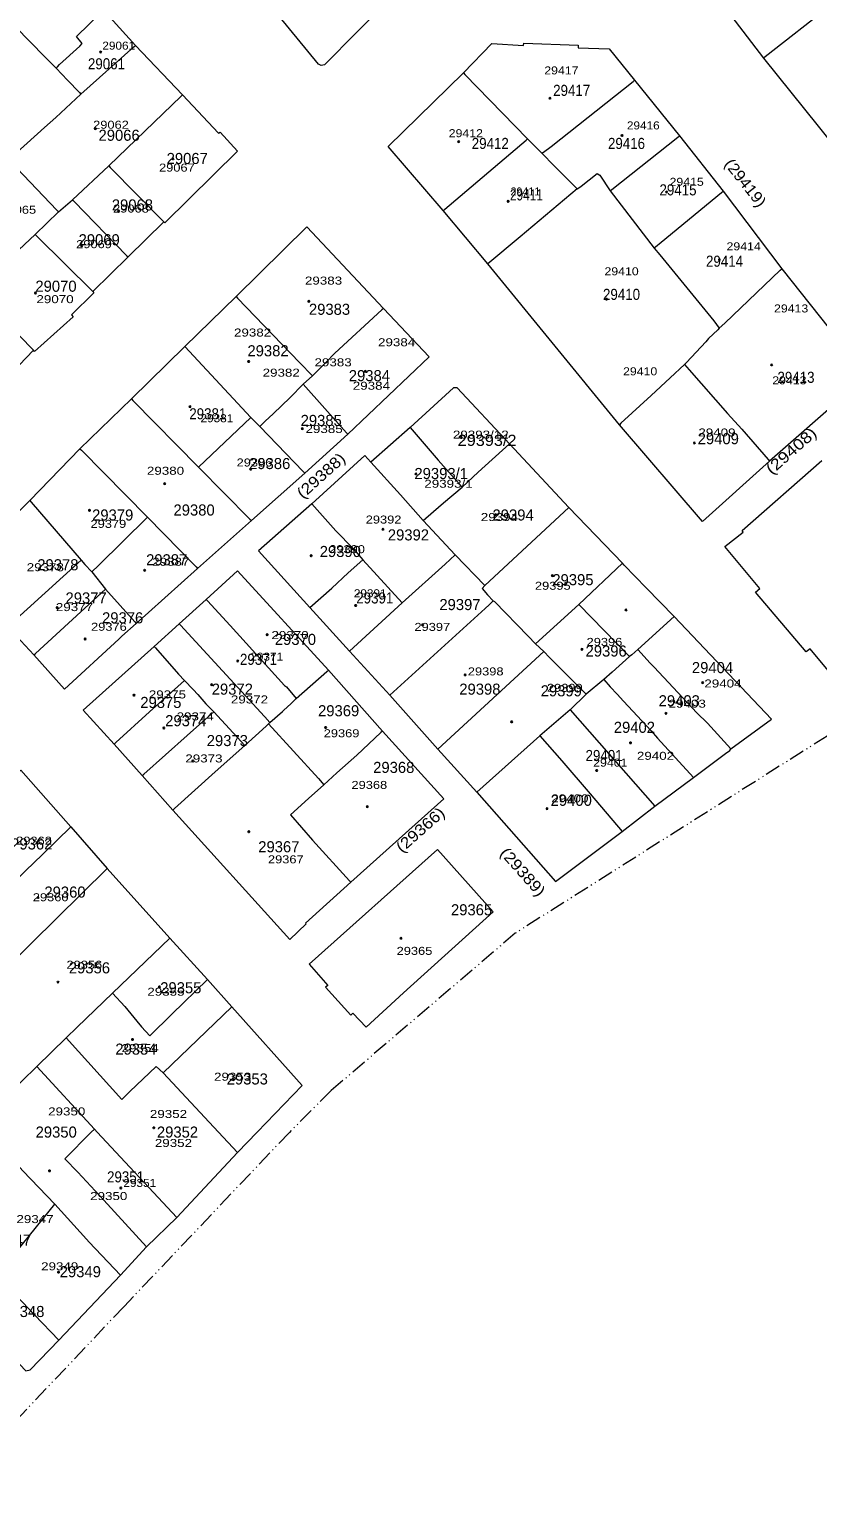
# Model space of a CAD drawing. Extents: x 650553 to 652508, y 239277 to 241647.
# Drawn here: x 651029.3 to 651285.4, y 239630 to 240108.2 of the extents above; entities that cross this region are included whole.
import ezdxf

# ---------------------------------------------------------------- set-up
doc = ezdxf.new("R2010")
doc.units = 0
doc.header["$PDMODE"] = 32
doc.header["$PDSIZE"] = 0.5
doc.linetypes.add('DASH_DOUBLE_DOT', pattern=[9.2, 5, -1.2, 0.3, -1.2, 0.3, -1.2])
for name, color, linetype in [('19', 7, 'Continuous'), ('20', 7, 'Continuous'), ('44', 7, 'Continuous'), ('6', 7, 'Continuous')]:
    doc.layers.add(name, color=color, linetype=linetype)
for name, color, linetype, lineweight in [('3', 7, 'Continuous', 13), ('5', 7, 'Continuous', 13), ('52', 7, 'DASH_DOUBLE_DOT', 13)]:
    doc.layers.add(name, color=color, linetype=linetype, lineweight=lineweight)

msp = doc.modelspace()

# ---------------------------------------------------------------- linework, layer by layer
at = {"layer": '3'}
for p, q in [((651178.3, 240032.05), (651163.79, 240049.38)), ((651301.48, 239995.66), (651269.84, 239967.99))]:
    msp.add_line(p, q, dxfattribs=at)
for points in [[(651146.21, 240118.01), (651125.2, 240096.68), (651124.15, 240096.5), (651123.22, 240096.94), (651100.89, 240124.15), (651084.81, 240142.79), (651068.91, 240161.72)], [(651014.69, 240119.32), (651031.37, 240136.47), (651033.06, 240136.27), (651053.41, 240114.49), (651063.76, 240102.95), (651079.09, 240086.95)], [(651244.93, 240128.08), (651253.33, 240117.93), (651267.91, 240098.88), (651285.64, 240076.82), (651301.47, 240056.95)], [(651170.33, 240094.05), (651179.61, 240103.61), (651189.88, 240103.02), (651189.94, 240103.72), (651207.67, 240103.1), (651207.61, 240102.24), (651217.69, 240101.92)], [(651217.69, 240101.92), (651225.95, 240091.72), (651240.57, 240073.58), (651254.7, 240055.63), (651273.8, 240030.45), (651301.48, 239995.66)], [(651163.79, 240049.38), (651145.92, 240070.2), (651170.33, 240094.05)], [(651079.09, 240086.95), (651090.77, 240074.52), (651091.28, 240074.79), (651096.87, 240068.6), (651073.27, 240045.33), (651072.98, 240045.66), (651061.347, 240034.304), (651049.86, 240023.09)], [(651079.8, 240005.23), (651096.45, 240021.44), (651119.4, 240044.04), (651144.33, 240017.58), (651159.24, 240001.88)], [(651269.84, 239967.99), (651248.04, 239948.37), (651221.04, 239979.79), (651178.3, 240032.05)], [(651049.86, 240023.09), (651050.21, 240022.68), (651042.96, 240015.47), (651043.52, 240014.85), (651030.93, 240003.62), (651030.64, 240004.03)], [(650963.63, 239979.83), (650963.19, 239979.42), (650984.08, 239956.68), (651007.923, 239979.861), (651007.45, 239980.27), (651019.018, 239991.973), (651030.64, 240004.03)], [(651079.8, 240005.23), (651062.449, 239988.199), (651045.708, 239971.989), (651029.394, 239955.14)], [(651063.98, 239915.24), (651067.961, 239918.8), (651083.95, 239933.1), (651101.47, 239948.63), (651118.77, 239964.05), (651132.76, 239976.69), (651159.24, 240001.88)], [(651294.154, 239893.589), (651283.07, 239907.03), (651281.72, 239905.99), (651265.26, 239925.42), (651266.66, 239926.6), (651255.322, 239940.281), (651261.29, 239944.93), (651260.89, 239945.47), (651286.79, 239968.16)], [(651029.394, 239955.14), (651011.428, 239937.153), (651010.901, 239937.895), (651005.075, 239932.349), (651009.776, 239926.918), (651010.311, 239927.45), (651022.23, 239914.101), (651030.731, 239905.003)], [(651086.75, 239923.04), (651096.89, 239932.32), (651126.46, 239900.08), (651144.02, 239880.27)], [(651046.81, 239887.11), (651069.8, 239907.8), (651077.97, 239915.13), (651086.75, 239923.04)], [(651030.731, 239905.003), (651040.74, 239893.93), (651058.4, 239910.11), (651059.31, 239911.07), (651063.98, 239915.24)], [(651133.77, 239831.17), (651119.06, 239817.88), (651119.22, 239817.67), (651113.96, 239812.53), (651075.92, 239854.63), (651065.92, 239865.85), (651056.86, 239876.06), (651046.81, 239887.11)], [(651144.02, 239880.27), (651163.99, 239858.27), (651154.68, 239849.922), (651133.77, 239831.17)], [(651000, 239839.83), (651003.18, 239842.9), (651002.08, 239844.3), (651026.48, 239867.54), (651042.7, 239849.13), (651054.6, 239835.68), (651074.89, 239813.04), (651087.13, 239799.56), (651095.02, 239790.72), (651117.9, 239765.17), (651103.31, 239750)], [(651161.96, 239841.85), (651120.21, 239804.61), (651126.28, 239797.58), (651125.52, 239797.04), (651133.7, 239787.96), (651134.35, 239788.6), (651138.68, 239784.1)], [(651138.68, 239784.1), (651150.81, 239795.25), (651180.03, 239821.6), (651161.96, 239841.85)], [(651000, 239701.81), (651009.47, 239692.08), (651028.09, 239672.47), (651029.48, 239672.78), (651038.83, 239682.45), (651058.85, 239703.52), (651067.38, 239712.72), (651077.17, 239722.24), (651096.93, 239743.36), (651103.31, 239750)]]:
    msp.add_lwpolyline(points, dxfattribs=at)
msp.add_lwpolyline([(651168.27, 239991.75), (651167.09, 239991.75), (651152.99, 239978.92), (651140.3, 239967.61), (651138.29, 239969.77), (651121.12, 239954.05), (651103.76, 239938.81), (651120.39, 239920.4), (651133.33, 239906.2), (651146.38, 239891.99), (651161.99, 239874.45), (651174.68, 239860.43), (651200.26, 239831.38), (651221.98, 239847.7), (651232.51, 239855.84), (651245.06, 239865.24), (651255.49, 239872.96), (651256.94, 239874), (651257.24, 239874.46), (651270.44, 239884.15), (651238.78, 239917.53), (651229.71, 239926.8), (651222.6, 239934.14), (651222.04, 239934.78), (651204.63, 239952.95), (651185.35, 239973.63)], close=True, dxfattribs=at)
at = {"layer": '44'}
msp.add_point((651223.163, 239919.63), dxfattribs=at)
at = {"layer": '5'}
for p, q in [((651117.05, 240000), (651121.24, 239995.65)), ((651101.26, 239982.09), (651084.27, 239966.04)), ((651177.27, 239927.53), (651204.63, 239952.95)), ((651207.89, 239921.39), (651224.33, 239904.48)), ((651196.49, 239906.1), (651161.99, 239874.45)), ((651205.01, 239887.21), (651232.51, 239855.84)), ((651072.72, 239769.3), (651090.73, 239750)), ((651049.41, 239750), (651050.41, 239751)), ((651051.34, 239750), (651077.17, 239722.24)), ((651090.73, 239750), (651096.93, 239743.36))]:
    msp.add_line(p, q, dxfattribs=at)
for points in [[(651014.69, 240119.32), (651015.181, 240118.82), (651034.33, 240099.34), (651038, 240095.56)], [(651292.21, 240117.87), (651291.71, 240117.48), (651289.7, 240115.91), (651268.41, 240099.271), (651267.91, 240098.88)], [(651038, 240095.56), (651038.454, 240096.06), (651039.09, 240096.76), (651045.68, 240102.8), (651046.44, 240103.65), (651044.58, 240105.87), (651052.91, 240114.002), (651053.41, 240114.49)], [(651046.01, 240087.16), (651063.26, 240102.505), (651063.76, 240102.95)], [(651038, 240095.56), (651041.65, 240091.75), (651045.535, 240087.66), (651046.01, 240087.16)], [(651170.33, 240094.05), (651170.817, 240093.55), (651191.2, 240072.64), (651195.86, 240067.97)], [(651195.86, 240067.97), (651196.36, 240068.335), (651198.83, 240070.14), (651225.45, 240091.322), (651225.95, 240091.72)], [(651022.59, 240065.87), (651025.24, 240068.24), (651034.21, 240076.35), (651037.83, 240079.55), (651046.01, 240087.16)], [(651055.09, 240063.85), (651078.59, 240086.469), (651079.09, 240086.95)], [(651218.08, 240055.75), (651218.58, 240056.146), (651240.07, 240073.184), (651240.57, 240073.58)], [(651163.79, 240049.38), (651164.29, 240049.804), (651190.7, 240072.216), (651191.2, 240072.64)], [(650998.84, 240012), (651011.61, 240023.38), (651031.17, 240041.53), (651038.69, 240048.96), (651043.31, 240052.81), (651055.09, 240063.85)], [(651022.59, 240065.87), (651023.066, 240065.37), (651038.214, 240049.46), (651038.69, 240048.96)], [(651055.09, 240063.85), (651055.582, 240063.35), (651072.98, 240045.66)], [(651195.86, 240067.97), (651199.88, 240063.83), (651207.3, 240056.4)], [(651207.3, 240056.4), (651207.8, 240056.731), (651208.57, 240057.24), (651213.83, 240061.34), (651214.64, 240060.82), (651218.08, 240055.75), (651232.29, 240037.13)], [(651207.3, 240056.4), (651188.75, 240040.77), (651178.3, 240032.05)], [(651232.29, 240037.13), (651232.79, 240037.536), (651234.64, 240039.04), (651254.2, 240055.216), (651254.7, 240055.63)], [(651043.31, 240052.81), (651043.797, 240052.31), (651060.86, 240034.804), (651061.347, 240034.304)], [(651031.17, 240041.53), (651031.67, 240041.037), (651049.86, 240023.09)], [(651232.29, 240037.13), (651234.21, 240034.97), (651251.72, 240013.58), (651253.47, 240011.13)], [(651253.47, 240011.13), (651255.28, 240012.81), (651273.3, 240029.974), (651273.8, 240030.45)], [(651011.61, 240023.38), (651012.102, 240022.88), (651030.64, 240004.03)], [(651096.45, 240021.44), (651096.93, 240020.94), (651117.05, 240000)], [(651144.33, 240017.58), (651143.83, 240017.117), (651128.58, 240003), (651125.58, 240000)], [(651253.47, 240011.13), (651252.97, 240010.649), (651249.99, 240007.78), (651249.17, 240006.71), (651242.81, 240000)], [(651079.8, 240005.23), (651101.26, 239982.09), (651101.63, 239981.68), (651104.14, 239979.23)], [(651125.58, 240000), (651121.24, 239995.65), (651118.3, 239992.97), (651114.07, 239988.67), (651108.46, 239983.27), (651105.95, 239980.97), (651104.14, 239979.23)], [(651242.81, 240000), (651242.2, 239999.36), (651237.54, 239995.03), (651231.31, 239989.29)], [(651242.2, 239999.36), (651243.65, 239997.64), (651256.16, 239983.44), (651260.83, 239978.29)], [(651118.3, 239992.97), (651132.316, 239977.19), (651132.76, 239976.69)], [(651062.449, 239988.199), (651062.941, 239987.699), (651084.27, 239966.04)], [(651231.31, 239989.29), (651221.54, 239980.253), (651221.04, 239979.79)], [(651104.14, 239979.23), (651118.288, 239964.55), (651118.77, 239964.05)], [(651152.99, 239978.92), (651162.13, 239968.22), (651169.91, 239959.54)], [(651260.83, 239978.29), (651269.403, 239968.49), (651269.84, 239967.99)], [(651157.3, 239948.69), (651160.64, 239951.57), (651163.91, 239954.38), (651169.91, 239959.54), (651175.17, 239964.33), (651185.35, 239973.63)], [(651045.708, 239971.989), (651046.202, 239971.489), (651067.66, 239949.79)], [(651084.27, 239966.04), (651100.976, 239949.13), (651101.47, 239948.63)], [(651140.3, 239967.61), (651149.84, 239956.99), (651157.3, 239948.69), (651167.62, 239937.56), (651177.27, 239927.53), (651176.41, 239926.54), (651178.14, 239924.57), (651179.99, 239922.6), (651180.39, 239922.41), (651191.41, 239911.06), (651193.79, 239908.56), (651196.49, 239906.1), (651198.36, 239904.19), (651206.33, 239896.2), (651210.21, 239892.24)], [(651029.394, 239955.14), (651029.827, 239954.64), (651046.15, 239935.78), (651047.3, 239934.35), (651049.54, 239931.95), (651054, 239926.42)], [(651121.12, 239954.05), (651128.9, 239945.37), (651134.46, 239939.55), (651137.69, 239935.94), (651150.39, 239921.89)], [(651049.54, 239931.95), (651051.7, 239934.03), (651067.66, 239949.79)], [(651067.66, 239949.79), (651083.462, 239933.6), (651083.95, 239933.1)], [(651022.23, 239914.101), (651022.73, 239914.554), (651046.15, 239935.78)], [(651120.39, 239920.4), (651127.61, 239926.74), (651132.9, 239931.66), (651137.69, 239935.94)], [(651133.33, 239906.2), (651150.39, 239921.89), (651164.35, 239934.48), (651167.62, 239937.56)], [(651193.79, 239908.56), (651207.89, 239921.39), (651222.04, 239934.78)], [(651030.731, 239905.003), (651031.231, 239905.463), (651054, 239926.42)], [(651054, 239926.42), (651063.534, 239915.74), (651063.98, 239915.24)], [(651086.75, 239923.04), (651087.205, 239922.54), (651094.51, 239914.52), (651112.15, 239895.09), (651112.85, 239894.63), (651115.97, 239890.83)], [(651146.38, 239891.99), (651177.35, 239920.12), (651178.75, 239921.32), (651179.99, 239922.6)], [(651238.78, 239917.53), (651226.97, 239906.78), (651225.11, 239905.07), (651224.33, 239904.48), (651218.7, 239899.4), (651215.95, 239897.08), (651210.21, 239892.24), (651205.01, 239887.21), (651195.17, 239878.74), (651174.68, 239860.43)], [(651077.97, 239915.13), (651078.429, 239914.63), (651105.64, 239884.96), (651105.8, 239884.86), (651107.43, 239883.02)], [(651069.8, 239907.8), (651070.242, 239907.3), (651077.79, 239898.77), (651079.74, 239896.73), (651082.47, 239893.76), (651083.97, 239892.12), (651086.67, 239889.15), (651089.21, 239886.48), (651099.26, 239875.59)], [(651226.97, 239906.78), (651228.07, 239905.62), (651230.9, 239902.44), (651232.29, 239900.99), (651246.14, 239886.24), (651249.62, 239882.79), (651257.24, 239874.46)], [(651056.86, 239876.06), (651057.36, 239876.515), (651068.34, 239886.51), (651075.38, 239892.8), (651079.74, 239896.73)], [(651115.97, 239890.83), (651125.96, 239899.639), (651126.46, 239900.08)], [(651215.95, 239897.08), (651218.03, 239894.65), (651220.31, 239892.25), (651222.36, 239889.94), (651231.37, 239880.31), (651233.46, 239877.99), (651245.06, 239865.24)], [(651075.92, 239854.63), (651076.42, 239855.083), (651089.61, 239867.04), (651099.26, 239875.59), (651106.24, 239881.87), (651107, 239882.62), (651107.43, 239883.02), (651111.55, 239886.66), (651111.96, 239887.03), (651114.27, 239889.17), (651115.97, 239890.83)], [(651065.92, 239865.85), (651066.42, 239866.294), (651080.58, 239878.86), (651084.6, 239882.37), (651089.21, 239886.48)], [(651107, 239882.62), (651123.22, 239864.89), (651125.01, 239862.78)], [(651144.02, 239880.27), (651143.52, 239879.799), (651135.69, 239872.43), (651129.22, 239866.71), (651125.01, 239862.78), (651119.97, 239858.37), (651114.12, 239853.08), (651121.29, 239844.86)], [(651195.17, 239878.74), (651202.33, 239870.58), (651211.53, 239859.88), (651221.98, 239847.7)], [(651003.18, 239842.9), (651010.69, 239834.98), (651015.18, 239829.88), (651015.37, 239829.53), (651018.95, 239825.92), (651028.04, 239834.93), (651033.56, 239840.23), (651042.7, 239849.13)], [(651121.29, 239844.86), (651133.314, 239831.67), (651133.77, 239831.17)], [(651001.83, 239783.86), (651011.83, 239793.51), (651018.25, 239799.79), (651021.7, 239803.27), (651054.6, 239835.68)], [(651012.96, 239753.01), (651021.99, 239761.78), (651031.72, 239771.33), (651041.21, 239780.58), (651044.83, 239784.08), (651056.34, 239795.18), (651074.89, 239813.04)], [(651056.34, 239795.18), (651060.27, 239790.81), (651064.25, 239786.04), (651065.75, 239784.18), (651068.37, 239781.33), (651075.54, 239788.36), (651087.13, 239799.56)], [(651041.21, 239780.58), (651059.28, 239760.61), (651061.95, 239763.15), (651070.53, 239771.27), (651072.72, 239769.3), (651095.02, 239790.72)], [(651031.72, 239771.33), (651050.41, 239751), (651051.34, 239750)], [(651017.51, 239748.19), (651027.12, 239737.39), (651037.52, 239726.58), (651047.83, 239715.28), (651048.66, 239714.26), (651058.85, 239703.52)], [(651049.41, 239750), (651040.77, 239741.31), (651045, 239736.96), (651053.44, 239727.93), (651067.38, 239712.72)], [(651009.47, 239692.08), (651018.73, 239703.44), (651037.52, 239726.58)], [(651018.73, 239703.44), (651022.99, 239698.95), (651030.9, 239690.63), (651038.83, 239682.45)]]:
    msp.add_lwpolyline(points, dxfattribs=at)
at = {"layer": '52'}
for points in [[(651375.157, 239936.971), (651356.663, 239923.28), (651304.088, 239888.503), (651187.159, 239814.585), (651127.357, 239763.518), (651113.762, 239749.917)], [(651113.762, 239749.917), (651060.054, 239693.394), (650999.992, 239629.999)]]:
    msp.add_lwpolyline(points, dxfattribs=at)
at = {"layer": '6'}
for p in [(651052.448, 240100.825), (651198.447, 240085.845), (651050.72, 240075.955), (651221.897, 240073.735), (651168.79, 240071.715), (651075.922, 240066.14), (651236.375, 240055.355), (651184.886, 240052.345), (651058.284, 240049.077), (651046.296, 240037.95), (651253.545, 240033.38), (651031.253, 240022.575), (651216.847, 240020.565), (651120.089, 240019.845), (651100.534, 240000.335), (651138.487, 239997.135), (651270.483, 239999.22), (651081.473, 239985.635), (651117.989, 239978.51), (651169.619, 239975.645), (651245.416, 239973.865), (651101.225, 239965.36), (651154.903, 239963.805), (651073.259, 239960.649), (651048.822, 239951.969), (651180.786, 239950.58), (651144.22, 239945.83), (651120.866, 239937.225), (651066.711, 239932.515), (651199.264, 239930.755), (651038.31, 239920.391), (651135.326, 239921.07), (651223.163, 239919.63), (651106.55, 239911.575), (651157.06, 239914.775), (651047.406, 239910.175), (651208.883, 239906.815), (651097.005, 239903.03), (651170.904, 239898.525), (651063.286, 239891.93), (651088.551, 239895.36), (651248.093, 239895.995), (651186.013, 239883.265), (651236.204, 239886.01), (651072.984, 239881.29), (651125.54, 239881.43), (651224.643, 239876.46), (651082.399, 239870.555), (651213.672, 239867.455), (651139.093, 239855.72), (651197.537, 239855.06), (651100.608, 239847.575), (651032.105, 239826.2), (651150.027, 239812.975), (651038.597, 239798.73), (651071.547, 239797.185), (651062.803, 239780.085), (651095.527, 239767.04), (651069.724, 239751.41), (651035.818, 239737.425), (651058.993, 239731.86), (651038.754, 239704.515)]:
    msp.add_point(p, dxfattribs=at)

# ---------------------------------------------------------------- texts
at = {"layer": '19'}
for s, width, p in [('29061', 0.9, (651048.308, 240095.228)), ('29417', 0.9, (651199.498, 240086.607)), ('29412', 0.9, (651173.039, 240069.364)), ('29416', 0.9, (651217.317, 240069.364)), ('29411', 0.8, (651185.458, 240052.66)), ('29415', 0.9, (651234.055, 240054.277)), ('29414', 0.9, (651249.173, 240031.108)), ('29410', 0.9, (651215.695, 240020.331)), ('29413', 0.9, (651272.392, 239993.39)), ('29381', 0.9, (651081.246, 239981.536)), ('29393/2', 1.1, (651168.45, 239972.914)), ('29391', 0.9, (651135.512, 239921.726)), ('29371', 0.9, (651097.715, 239901.789)), ('29401', 0.9, (651210.028, 239870.537)), ('29351', 0.9, (651054.518, 239733.676))]:
    msp.add_text(s, height=3.6, dxfattribs=dict(at, width=width)).set_placement(p)
for s, p in [('29066', (651051.745, 240072.016)), ('29067', (651073.884, 240064.472)), ('29068', (651056.065, 240049.385)), ('29069', (651045.266, 240038.07)), ('29070', (651031.227, 240022.983)), ('29383', (651120.124, 240015.482)), ('29382', (651100.145, 240002.012)), ('29384', (651133.082, 239993.929)), ('29385', (651117.424, 239979.381)), ('29409', (651246.474, 239973.453)), ('29386', (651100.685, 239965.372)), ('29393/1', (651154.411, 239962.138)), ('29380', (651076.116, 239950.284)), ('29379', (651049.658, 239948.667)), ('29394', (651179.79, 239948.667)), ('29392', (651145.772, 239942.201)), ('29390', (651123.634, 239936.813)), ('29378', (651031.839, 239932.503)), ('29387', (651067.207, 239934.12)), ('29395', (651199.229, 239927.653)), ('29377', (651041.018, 239921.726)), ('29397', (651162.511, 239919.571)), ('29376', (651052.897, 239915.26)), ('29370', (651109.054, 239908.255)), ('29396', (651210.028, 239904.483)), ('29404', (651244.586, 239899.095)), ('29372', (651088.536, 239892.091)), ('29398', (651168.991, 239892.09)), ('29399', (651195.449, 239891.552)), ('29403', (651233.786, 239888.319)), ('29375', (651065.317, 239887.78)), ('29369', (651123.093, 239885.086)), ('29374', (651073.417, 239881.853)), ('29402', (651219.207, 239879.697)), ('29373', (651086.916, 239875.387)), ('29368', (651141.006, 239866.681)), ('29400', (651198.689, 239855.989)), ('29362', (651023.361, 239841.807)), ('29367', (651103.654, 239840.902)), ('29360', (651034.161, 239826.181)), ('29365', (651166.291, 239820.426)), ('29356', (651042.099, 239801.568)), ('29355', (651071.797, 239795.102)), ('29354', (651057.217, 239775.166)), ('29353', (651093.396, 239765.467)), ('29350', (651031.299, 239748.224)), ('29352', (651070.717, 239748.224)), ('29347', (651016.46, 239713.106)), ('29349', (651039.139, 239702.868)), ('29348', (651020.779, 239689.937))]:
    msp.add_text(s, height=3.6, dxfattribs=at).set_placement(p)
for s, rotation, width, p in [('(29419)', 308.324, 1.1, (651254.918, 240064.42)), ('(29408)', 41.389, 1.2, (651270.566, 239963.382)), ('(29388)', 42.016, 1.15, (651118.168, 239955.543)), ('(29366)', 41.456, 1.15, (651150.356, 239840.55)), ('(29389)', 311.554, 1.15, (651181.975, 239840.499))]:
    msp.add_text(s, height=3.6, rotation=rotation, dxfattribs=dict(at, width=width)).set_placement(p)
at = {"layer": '20'}
for s, width, p in [('29061', 1.1, (651052.995, 240101.625)), ('29417', 1.15, (651196.611, 240093.574)), ('29062', 1.2, (651049.995, 240075.93)), ('29416', 1.1, (651223.473, 240075.708)), ('29412', 1.15, (651165.559, 240073.184)), ('29067', 1.2, (651071.416, 240062)), ('29415', 1.15, (651237.326, 240057.395)), ('29065', 1.2, (651019.868, 240048.317)), ('29068', 1.2, (651056.488, 240048.699)), ('29069', 1.2, (651044.48, 240037.133)), ('29414', 1.15, (651255.85, 240036.431)), ('29410', 1.15, (651216.176, 240028.325)), ('29383', 1.25, (651118.834, 240025.305)), ('29070', 1.25, (651031.571, 240019.272)), ('29413', 1.15, (651271.278, 240016.261)), ('29382', 1.25, (651095.777, 240008.434)), ('29384', 1.25, (651142.587, 240005.276)), ('29382', 1.25, (651105.076, 239995.397)), ('29383', 1.25, (651121.944, 239998.762)), ('29410', 1.15, (651222.212, 239995.833)), ('29384', 1.25, (651134.38, 239991.151)), ('29413', 1.15, (651270.701, 239992.9)), ('29381', 1.1, (651084.905, 239980.601)), ('29385', 1.25, (651119.022, 239977.091)), ('29393/12', 1.25, (651166.923, 239975.274)), ('29409', 1.25, (651246.688, 239975.972)), ('29386', 1.2, (651096.624, 239966.219)), ('29380', 1.25, (651067.477, 239963.533)), ('29393/1 ', 1.25, (651157.628, 239959.315)), ('29392', 1.2, (651138.588, 239947.683)), ('29394', 1.25, (651175.972, 239948.496)), ('29379', 1.2, (651049.149, 239946.277)), ('29390', 1.2, (651126.72, 239938.065)), ('29378', 1.25, (651028.424, 239932.206)), ('29387', 1.25, (651069.192, 239933.977)), ('29391', 1.1, (651134.722, 239923.745)), ('29395', 1.2, (651193.58, 239926.175)), ('29377', 1.25, (651037.886, 239919.249)), ('29376', 1.2, (651049.319, 239912.858)), ('29370', 1.25, (651107.956, 239910.167)), ('29397', 1.2, (651154.425, 239912.816)), ('29396', 1.2, (651210.37, 239907.937)), ('29371', 1.1, (651101.101, 239903.152)), ('29398', 1.2, (651171.772, 239898.354)), ('29404', 1.25, (651248.639, 239894.43)), ('29375', 1.25, (651068.1, 239890.878)), ('29372', 1.25, (651094.764, 239889.249)), ('29399', 1.2, (651197.503, 239893.024)), ('29403', 1.25, (651237.037, 239887.875)), ('29374', 1.25, (651077.135, 239883.738)), ('29369', 1.2, (651124.938, 239878.265)), ('29373', 1.25, (651079.961, 239870.086)), ('29402', 1.25, (651226.719, 239870.939)), ('29401', 1.15, (651212.518, 239868.73)), ('29368', 1.2, (651133.96, 239861.481)), ('29400', 1.25, (651198.885, 239857.117)), ('29362', 1.2, (651024.985, 239843.374)), ('29367', 1.2, (651106.814, 239837.308)), ('29360', 1.2, (651030.393, 239824.995)), ('29356', 1.2, (651041.333, 239803.082)), ('29365', 1.2, (651148.632, 239807.579)), ('29355', 1.25, (651067.605, 239794.308)), ('29354', 1.25, (651059.238, 239776.003)), ('29353', 1.25, (651089.29, 239766.695)), ('29350', 1.25, (651035.368, 239755.426)), ('29352', 1.25, (651068.441, 239754.599)), ('29352', 1.25, (651070.051, 239745.182)), ('29351', 1.1, (651059.831, 239732.191)), ('29350', 1.25, (651049.028, 239727.936)), ('29347', 1.25, (651025.068, 239720.458)), ('29349', 1.25, (651033.088, 239705.115))]:
    msp.add_text(s, height=2.6, dxfattribs=dict(at, width=width)).set_placement(p)
msp.add_text('29411', height=2.6, dxfattribs=at).set_placement((651185.643, 240054.26))

doc.saveas('drawing.dxf')
